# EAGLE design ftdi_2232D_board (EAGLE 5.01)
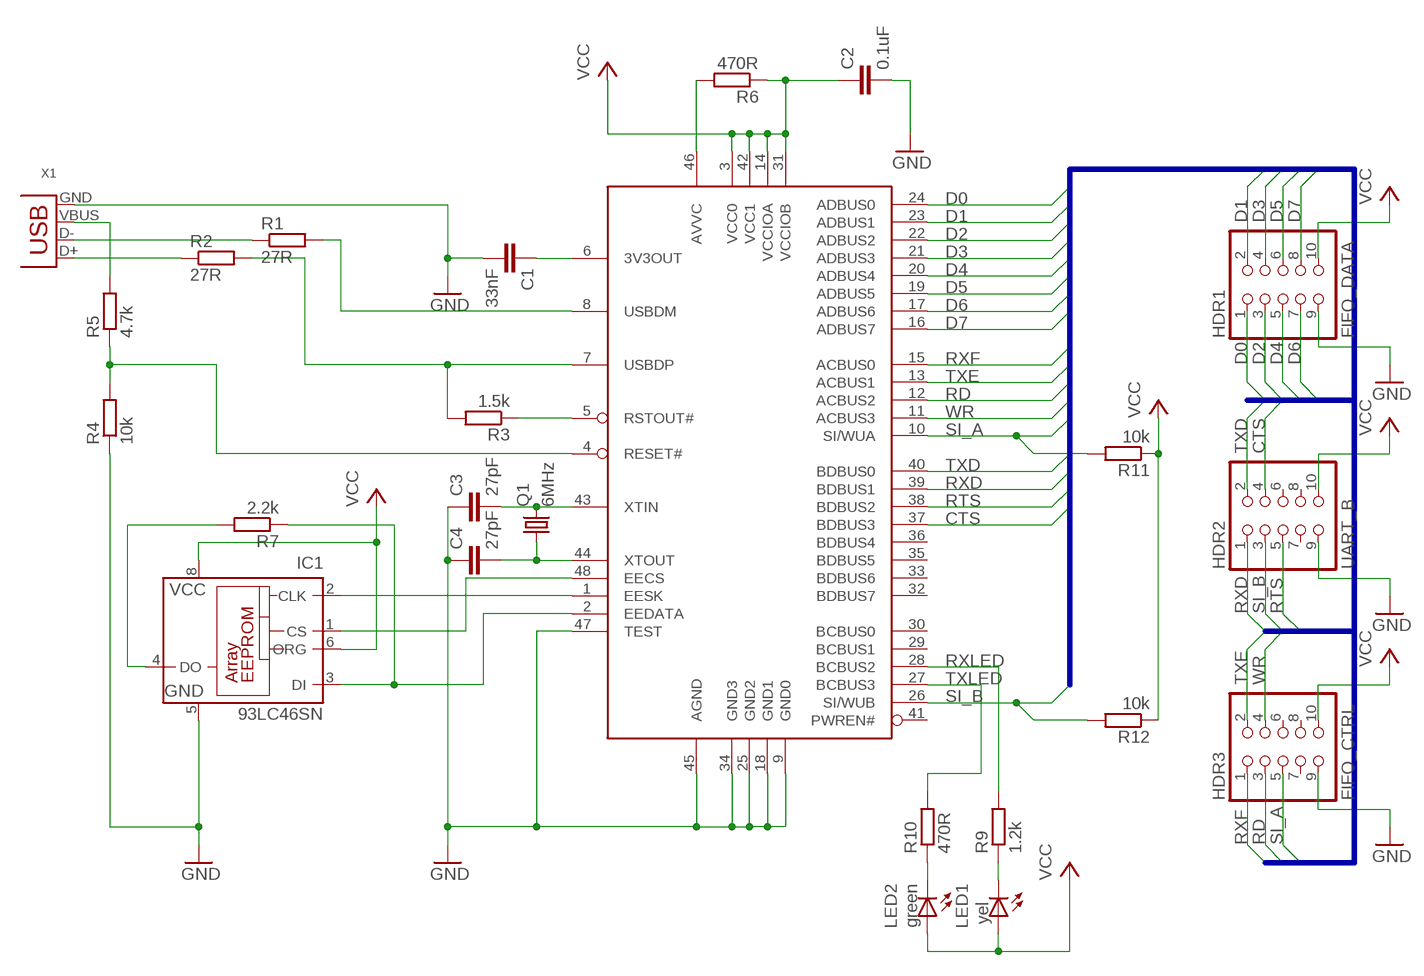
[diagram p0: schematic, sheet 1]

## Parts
C1  33nF  C-EUC0805  [C0805]
C2  0.1uF  C-EUC0805  [C0805]
C3  27pF  C-EUC0805  [C0805]
C4  27pF  C-EUC0805  [C0805]
HDR1  FIFO_DATA  PINHD-2X5  [2X05]
HDR2  UART_B  PINHD-2X5  [2X05]
HDR3  FIFO_CTRL  PINHD-2X5  [2X05]
IC1  93LC46SN  [SO-08]
LED1  yel  LEDSMT1206  [1206]
LED2  green  LEDSMT1206  [1206]
Q1  6MHz  CRYSTALHC49U70  [HC49U70]
R1  27R  R-EU_R0805  [R0805]
R2  27R  R-EU_R0805  [R0805]
R3  1.5k  R-EU_R0805  [R0805]
R4  10k  R-EU_R0805  [R0805]
R5  4.7k  R-EU_R0805  [R0805]
R6  470R  R-EU_R0805  [R0805]
R7  2.2k  R-EU_R0805  [R0805]
R9  1.2k  R-EU_R0805  [R0805]
R10  470R  R-EU_R0805  [R0805]
R11  10k  R-EU_R0805  [R0805]
R12  10k  R-EU_R0805  [R0805]
U1  FT2232D  FT2232L  [LQFP48]
X1  USBCON  USB-B-H  [USB-B-H]

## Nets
CTS: HDR2.4 U1.37(BDBUS3)
D0: HDR1.1 U1.24(ADBUS0)
D1: HDR1.2 U1.23(ADBUS1)
D2: HDR1.3 U1.22(ADBUS2)
D3: HDR1.4 U1.21(ADBUS3)
D4: HDR1.5 U1.20(ADBUS4)
D5: HDR1.6 U1.19(ADBUS5)
D6: HDR1.7 U1.17(ADBUS6)
D7: HDR1.8 U1.16(ADBUS7)
GND: C1.2 C2.2 C3.1 C4.1 HDR1.9 HDR2.9 HDR3.9 IC1.5(GND) R4.1 U1.9(GND0) U1.18(GND1) U1.25(GND2) U1.34(GND3) U1.45(AGND) U1.47(TEST) X1.GND
N$1: IC1.3(DI) R7.1 U1.2(EEDATA)
N$2: IC1.4(DO) R7.2
N$3: C3.2 Q1.2 U1.43(XTIN)
N$4: C4.2 Q1.1 U1.44(XTOUT)
N$5: IC1.2(CLK) U1.1(EESK)
N$6: IC1.1(CS) U1.48(EECS)
N$8: C1.1 U1.6(3V3OUT)
N$9: R3.1 U1.5(RSTOUT#)
N$10: R2.2 R3.2 U1.7(USBDP)
N$11: R1.2 U1.8(USBDM)
N$12: R6.2 U1.46(AVVC)
N$13: LED1.C R9.1
N$14: LED2.C R10.1
N$15: R2.1 X1.D+
N$16: R1.1 X1.D-
N$17: R5.2 X1.VBUS
N$18: R4.2 R5.1 U1.4(RESET#)
RD: HDR3.3 U1.12(ACBUS2)
RTS: HDR2.5 U1.38(BDBUS2)
RXD: HDR2.1 U1.39(BDBUS1)
RXF: HDR3.1 U1.15(ACBUS0)
RXLED: R9.2 U1.28(BCBUS2)
SI_A: HDR3.5 R11.2 U1.10(SI/WUA)
SI_B: HDR2.3 R12.2 U1.26(SI/WUB)
TXD: HDR2.2 U1.40(BDBUS0)
TXE: HDR3.2 U1.13(ACBUS1)
TXLED: R10.2 U1.27(BCBUS3)
VCC: C2.1 HDR1.10 HDR2.10 HDR3.10 IC1.6(ORG) IC1.8(VCC) LED1.A LED2.A R6.1 R11.1 R12.1 U1.3(VCC0) U1.14(VCCIOA) U1.31(VCCIOB) U1.42(VCC1)
WR: HDR3.4 U1.11(ACBUS3)
Unconnected: HDR2.6 HDR2.7 HDR2.8 HDR3.6 HDR3.7 HDR3.8 IC1.7(NU) U1.29(BCBUS1) U1.30(BCBUS0) U1.32(BDBUS7) U1.33(BDBUS6) U1.35(BDBUS5) U1.36(BDBUS4) U1.41(PWREN#)

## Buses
D[0..7],RXF,TXE,RD,WR,SI_A,TXD,RXD,RTS,CTS,SI_B

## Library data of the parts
C1-C4 = rcl:C-EU: CAPACITOR, European symbol
HDR1-HDR3 = pinhead:PINHD-2X5: PIN HEADER
IC1 = microchip:93*: Serial EPROM 1 K/2 K/4 K, low voltage, Microwire
LED1 LED2 = led:LED: LED
Q1 = crystal:CRYSTAL: CRYSTAL
R1-R7 R9-R12 = rcl:R-EU_: RESISTOR, European symbol
U1 = ftdichip-3:FT2232L: USB UART / FIFO Controller 3nd Generation USB Double-UART (USB <-> Serial) - FIFO Controller
X1 = con-usb-3:USB: USB Connectors

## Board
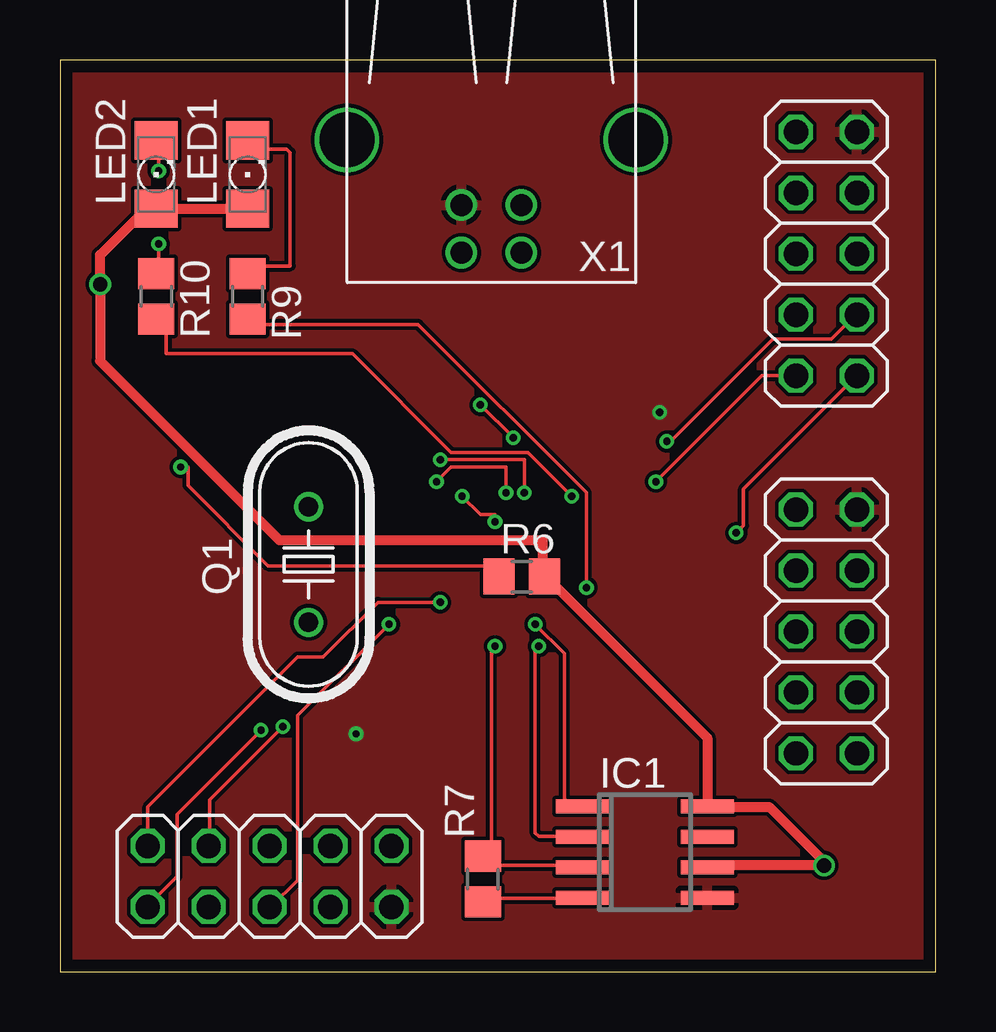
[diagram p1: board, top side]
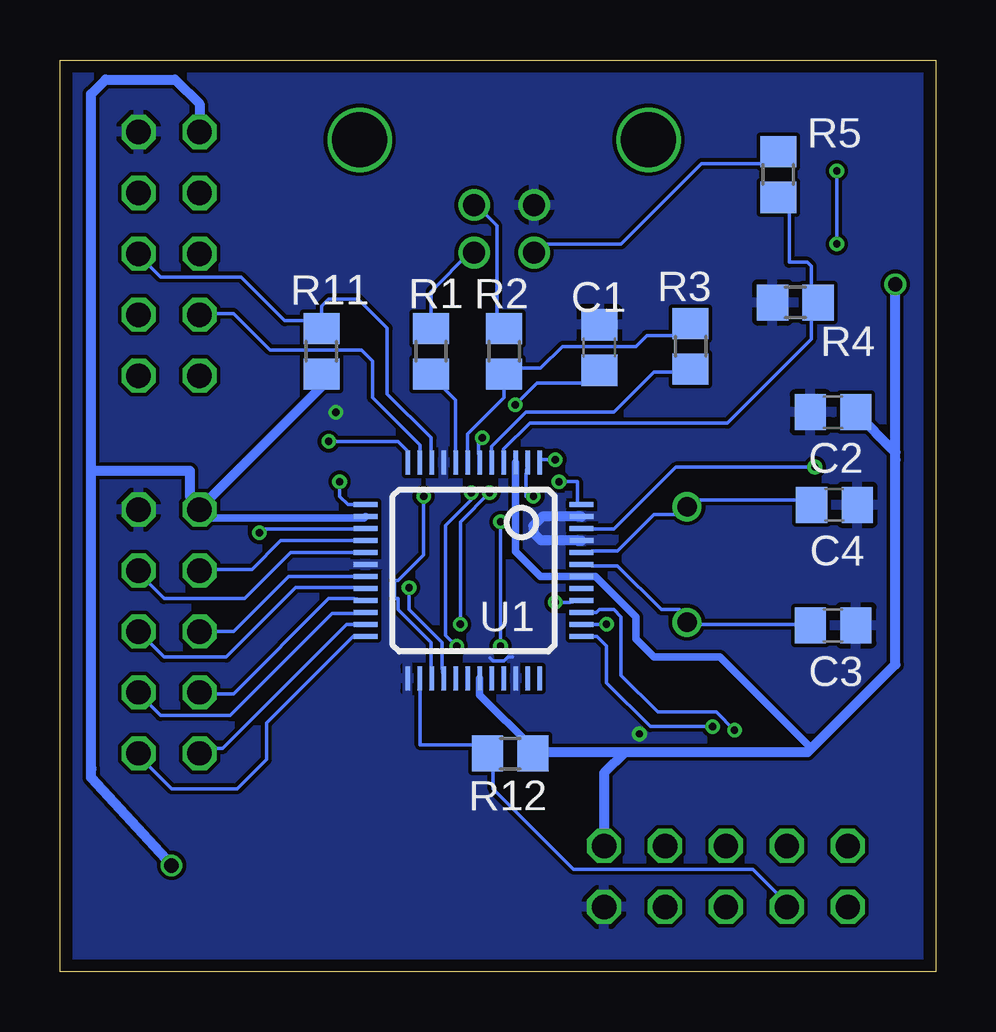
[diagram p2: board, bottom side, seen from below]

Size 36.5 x 38 mm. Coordinates in mm from the lower left corner, seen from the top.
Outline: 0,0 36.5,0 36.5,38 0,38 0,0
Copper layers (1*16): Top 0.035mm / dielectric 1.5mm / Bottom 0.035mm
Design rules "PCB-POOL *": minimum track width 6mil, minimum drill 12mil, track to track 6mil, track to pad 6mil, pad to pad 6mil, via to via 6mil, smd to smd 6mil, copper to edge 20mil, drill to drill 8mil, minimum pad ring 8mil, minimum via ring 6mil, stop-mask expansion 3mil, vias tented up to drill 0mil, thermal gap 8mil

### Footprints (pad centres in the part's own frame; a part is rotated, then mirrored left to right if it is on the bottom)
C0805 = smd 1.3 x 1.5: 1 -0.95,0; 2 0.95,0
2X05 = drill 1.016 octagon: 1 -5.08,-1.27; 2 -5.08,1.27; 3 -2.54,-1.27; 4 -2.54,1.27; 5 0,-1.27; 6 0,1.27; 7 2.54,-1.27; 8 2.54,1.27; 9 5.08,-1.27; 10 5.08,1.27
SO-08 = smd 0.6 x 2.2: 1 -1.905,-2.6; 2 -0.635,-2.6; 3 0.635,-2.6; 4 1.905,-2.6; 5 1.905,2.6; 6 0.635,2.6; 7 -0.635,2.6; 8 -1.905,2.6
1206 = smd 1.6 x 1.803: A -1.422,0; C 1.422,0
HC49U70 = drill 0.813 round: 1 -2.413,0; 2 2.413,0
R0805 = smd 1.3 x 1.5: 1 -0.95,0; 2 0.95,0
LQFP48 = smd 0.2 x 1: 1 -2.75,-4.5; 2 -2.25,-4.5; 3 -1.75,-4.5; 4 -1.25,-4.5; 5 -0.75,-4.5; 6 -0.25,-4.5; 7 0.25,-4.5; 8 0.75,-4.5; 9 1.25,-4.5; 10 1.75,-4.5; 11 2.25,-4.5; 12 2.75,-4.5; 25 2.75,4.5; 26 2.25,4.5; 27 1.75,4.5; 28 1.25,4.5; 29 0.75,4.5; 30 0.25,4.5; 31 -0.25,4.5; 32 -0.75,4.5; 33 -1.25,4.5; 34 -1.75,4.5; 35 -2.25,4.5; 36 -2.75,4.5 | smd 1 x 0.2: 13 4.5,-2.75; 14 4.5,-2.25; 15 4.5,-1.75; 16 4.5,-1.25; 17 4.5,-0.75; 18 4.5,-0.25; 19 4.5,0.25; 20 4.5,0.75; 21 4.5,1.25; 22 4.5,1.75; 23 4.5,2.25; 24 4.5,2.75; 37 -4.5,2.75; 38 -4.5,2.25; 39 -4.5,1.75; 40 -4.5,1.25; 41 -4.5,0.75; 42 -4.5,0.25; 43 -4.5,-0.25; 44 -4.5,-0.75; 45 -4.5,-1.25; 46 -4.5,-1.75; 47 -4.5,-2.25; 48 -4.5,-2.75
USB-B-H = drill 0.914 round: D+ 0,1.25; D- 1.981,1.25; GND 0,-1.25; VBUS 1.981,-1.25 | drill 2.286 round: P$1 -2.718,-6.02; P$2 -2.718,6.02

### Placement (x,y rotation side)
C1  14.02,26.01 90 bottom
C2  4.27,23.32 180 bottom
C3  4.27,14.43 180 bottom
C4  4.22,19.46 180 bottom
HDR1  31.95,14.17 90 top
HDR2  8.74,3.96 0 top
HDR3  31.95,29.92 90 top
IC1  24.38,4.98 270 top
LED1  7.82,33.22 90 top
LED2  4.01,33.22 90 top
Q1  10.36,16.97 270 top
R1  21.03,25.86 270 bottom
R2  17.98,25.86 270 bottom
R3  10.21,26.06 90 bottom
R4  5.84,27.89 0 bottom
R5  6.55,33.22 90 bottom
R6  19.25,16.46 180 top
R7  17.63,3.86 270 top
R9  7.82,28.14 270 top
R10  4.01,28.14 270 top
R11  25.6,25.86 90 bottom
R12  17.73,9.09 180 bottom
U1  19.25,16.71 180 bottom
X1  17.98,31.95 270 top

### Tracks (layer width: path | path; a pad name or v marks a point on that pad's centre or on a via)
CTS  (via drill 0.3)
  Top 0.152: v9.3,10.21 6.25,7.16 6.25,5.79 HDR2.4
  Bottom 0.152: U1.37 14.12,13.96 13.72,13.56 13.72,12.04 11.89,10.21 v9.3,10.21
D0
  Bottom 0.152: U1.24 24.29,13.96 27.89,10.36 27.89,8.84 29.11,7.62 31.85,7.62 33.22,8.99 HDR1.1
D1
  Bottom 0.152: U1.23 24.55,14.46 29.72,9.3 30.33,9.3 30.63,8.99 30.68,9.04 HDR1.2
D2
  Bottom 0.152: U1.22 24.23,14.94 25.15,14.94 29.41,10.67 32.31,10.67 33.22,11.58 HDR1.3
D3
  Bottom 0.152: U1.21 24.23,15.54 25.3,15.54 29.26,11.58 30.02,11.58 HDR1.4
D4
  Bottom 0.152: U1.20 24.23,16 26.67,16 29.57,13.11 32.16,13.11 HDR1.5
D5
  Bottom 0.152: U1.19 24.23,16.46 26.98,16.46 29.26,14.17 HDR1.6
D6
  Bottom 0.152: U1.17 26.89,17.46 28.8,15.54 32.16,15.54 33.22,16.61 HDR1.7
D7
  Bottom 0.152: U1.16 27.3,17.96 28.5,16.76 30.79,16.76 30.73,16.71 HDR1.8
GND  (via drill 0.3)
  Bottom 0.152: 17.65,13.12 17.83,13.11 17.98,12.95 18.44,12.95 18.57,13.07
  Bottom 0.406: U1.47 16.39,18.96 16.76,18.59 16.76,18.29 16.46,17.98 14.94,17.98 14.91,17.96 U1.45
  other vias: 12.34,9.91 24.99,23.32
  pour Bottom: -2.29,46.93 37.85,46.93 37.85,-1.78 -2.29,-1.78
  pour Top: -3.56,48.2 39.12,48.2 39.12,-3.05 -3.56,-3.05
N$1  (via drill 0.3)
  Top 0.152: v16.76,19.81 17.53,19.05 18.14,19.05 v18.14,18.75 | v18.14,13.56 17.98,13.41 17.98,5.33 R7.1 18.29,4.42 20.73,4.42 IC1.3
  Bottom 0.152: v16.76,19.81 17.07,19.81 17.07,20.73 U1.2 | v18.14,13.56 v18.14,18.75
N$2
  Top 0.152: R7.2 18.29,3.05 20.73,3.05 IC1.4
N$3
  Bottom 0.152: U1.43 14.33,16.92 13.26,16.92 11.43,15.09 10.67,15.09 Q1.2 9.91,14.48 5.79,14.48 C3.2
N$4
  Bottom 0.152: U1.44 14.33,17.53 13.26,17.53 11.73,19.05 10.82,19.05 Q1.1 9.91,19.66 5.79,19.66 C4.2
N$5  (via drill 0.3)
  Top 0.152: v15.85,21.34 19.36,21.34 v19.36,19.96 | v19.96,13.56 19.81,13.41 19.81,5.79 19.96,5.64 20.73,5.64 IC1.2
  Bottom 0.152: v15.85,21.34 16.46,21.34 U1.1 | v19.36,19.96 19.36,19.66 20.42,18.59 20.42,14.02 v19.96,13.56
N$6  (via drill 0.3)
  Top 0.152: v15.7,20.42 16.31,21.03 18.59,21.03 v18.59,19.96 | v19.81,14.48 21.03,13.26 21.03,7.16 IC1.1
  Bottom 0.152: v15.7,20.42 14.94,20.42 14.94,19.51 U1.48 | v18.59,19.96 19.81,18.75 v19.81,14.48
N$8  (via drill 0.3)
  Top 0.152: v17.53,23.62 v18.9,22.25
  Bottom 0.152: v18.9,22.25 19.05,22.25 19.05,21.64 U1.6 | v17.53,23.62 16.61,24.54 14.63,24.54 C1.1
N$9
  Bottom 0.152: U1.5 18.5,21.88 17.07,23.32 13.41,23.32 11.73,24.99 10.36,24.99 10.25,25.11 R3.1
N$10
  Bottom 0.152: U1.7 19.5,22.4 19.51,22.4 17.98,23.93 R2.2 17.37,25.15 16.46,25.15 15.54,26.06 12.5,26.06 12.04,26.52 10.82,26.52 R3.2
N$11
  Bottom 0.152: R1.2 21.03,24.84 20,23.81 U1.8
N$12  (via drill 0.3)
  Top 0.152: v5.03,21.03 5.33,21.03 5.33,20.27 8.69,16.92 17.68,16.92 R6.2
  Bottom 0.152: v5.03,21.03 10.82,21.03 13.41,18.44 14.33,18.44 U1.46
N$13
  Top 0.152: R9.1 8.53,29.41 9.6,29.41 9.6,34.14 9.45,34.29 8.69,34.29 LED1.C
N$14  (via drill 0.3)
  Top 0.152: v4.12,30.33 4.12,29.72 R10.1 | v4.12,33.38 4.12,33.98 LED2.C
  Bottom 0.152: v4.12,30.33 v4.12,33.38
N$15
  Bottom 0.152: R2.1 18.29,27.43 18.29,31.09 19.2,32 19.23,31.97 X1.D+
N$16
  Bottom 0.152: X1.D- 19.3,29.97 19.36,30.02 21.03,28.35 R1.1
N$17
  Bottom 0.152: R5.2 7.16,33.68 9.75,33.68 13.11,30.33 16.31,30.33 X1.VBUS
N$18
  Bottom 0.152: R5.1 6.1,31.7 6.1,29.57 5.33,29.57 5.18,29.41 5.18,28.5 R4.2 5.18,27.28 5.18,26.36 8.69,22.86 16.92,22.86 18,21.77 U1.4
RD  (via drill 0.3)
  Top 0.152: v25.3,22.1 25.45,22.1 29.72,26.36 32.16,26.36 33.17,27.38 HDR3.3
  Bottom 0.152: U1.12 22,21.7 22.4,22.1 v25.3,22.1
RTS  (via drill 0.3)
  Top 0.152: v13.72,14.48 9.91,10.67 9.91,3.81 8.79,2.69 HDR2.5
  Bottom 0.152: v13.72,14.48 14.33,14.48 U1.38
RXD  (via drill 0.3)
  Top 0.152: HDR2.1 3.66,2.74 4.88,3.96 4.88,6.55 v8.38,10.06
  Bottom 0.152: v8.38,10.06 9.14,10.82 11.58,10.82 13.11,12.34 13.11,14.78 13.41,15.09 14.02,15.09 14.14,14.96 U1.39
RXF  (via drill 0.3)
  Top 0.152: HDR3.1 28.5,20.12 28.5,18.59 v28.19,18.29
  Bottom 0.152: v28.19,18.29 28.19,18.44 24.23,18.44 U1.15
RXLED  (via drill 0.3)
  Top 0.152: v21.95,16 21.95,19.96 14.94,26.98 8.53,26.98 R9.2
  Bottom 0.152: v21.95,16 21.95,15.09 20.57,13.72 20.57,12.65 U1.28
SI_A
  Bottom 0.152: U1.10 21,21.46 21.03,21.49 21.03,22.25 22.86,24.08 22.86,26.82 24.08,28.04 25.3,28.04 25.6,27.74 R11.2 26.21,27.13 27.13,27.13 28.96,28.96 32.31,28.96 33.22,29.87 HDR3.5
SI_B
  Bottom 0.152: U1.26 21.49,11.73 21.49,9.45 19.2,9.45 R12.2 18.44,8.38 18.44,7.62 15.09,4.27 7.62,4.27 7.32,3.96 | 7.32,3.96 7.16,3.81 | HDR2.3 6.2,2.85 7.32,3.96
TXD  (via drill 0.3)
  Top 0.152: v15.85,15.39 13.26,15.39 10.97,13.11 9.91,13.11 3.66,6.86 HDR2.2
  Bottom 0.152: v15.85,15.39 15.24,15.39 U1.40
TXE  (via drill 0.3)
  Top 0.152: v24.84,20.42 29.26,24.84 HDR3.2
  Bottom 0.152: U1.13 24.49,19.46 24.84,19.81 v24.84,20.42
TXLED  (via drill 0.3)
  Top 0.152: v21.34,19.81 19.51,21.64 16.31,21.64 12.19,25.76 4.42,25.76 4.42,26.67 R10.2
  Bottom 0.152: v21.34,19.81 21.34,17.37 22.4,16.31 22.55,16.31 22.55,15.54 22.4,15.54 22.4,15.09 21.03,13.72 21.03,12.65 U1.27
VCC  (via drill 0.6)
  Top 0.406: LED1.A 7.82,31.7 7.72,31.8 LED2.A 3.61,31.8 1.68,29.87 v1.68,28.65 1.68,25.45 9.14,17.98 20.12,17.98 20.12,16.55 R6.1 | R6.1 20.27,16.46 | R6.1 20.36,16.31 20.42,16.31 26.98,9.74 IC1.8 27.1,6.88 27.13,6.86 29.57,6.86 32,4.42 v31.85,4.42 27.58,4.42 27.43,4.27 27.36,4.34 IC1.6
  Bottom 0.305: U1.14 23.82,18.9 30.33,18.9 HDR1.10 | R12.1 16.78,9.28 16.76,9.3 19,11.54 U1.31 | U1.3 17.5,17.5 16.46,16.46 14.48,16.46 U1.42 14.18,16.46 12.5,14.78 12.5,13.87 11.73,13.11 8.99,13.11 5.18,9.3
  Bottom 0.406: R11.1 25.6,24.38 30.68,19.3 HDR1.10 31.09,19.81 31.09,20.88 35.2,20.88 | 3.32,23.28 C2.1 3.35,23.32 1.68,21.64 1.68,21.34 | R12.1 16.78,9.13 16.76,9.14 12.95,9.14 | 12.95,9.14 5.33,9.14 5.18,9.3 1.68,12.8 1.68,21.34 | HDR2.10 13.82,8.28 12.95,9.14 | 1.68,21.34 v1.68,28.65 | HDR3.10 30.68,36.17 31.7,37.19 34.59,37.19 35.2,36.58 35.2,20.88 | 35.2,8.53 35.2,20.88 | 35.2,8.53 35.2,8.38 | 35.2,8.53 35.2,8.08 v31.85,4.42
WR
  Bottom 0.152: U1.11 21.49,21.64 21.49,21.95 23.47,23.93 23.47,25.45 23.93,25.91 27.74,25.91 29.26,27.43 30.02,27.43 HDR3.4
